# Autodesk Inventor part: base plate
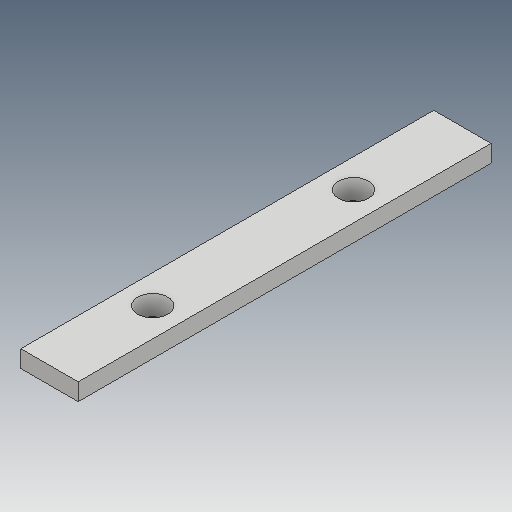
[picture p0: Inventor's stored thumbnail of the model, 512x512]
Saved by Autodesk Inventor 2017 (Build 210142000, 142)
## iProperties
Created: 2016-03
Part Number: base plate
Material: Generic
Document SubType Name: Modeling
Designer: Sandeep
Density: 1 g/cm^3
Appearance: Default
Author: Sandeep
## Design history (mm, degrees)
sketch "Sketch1"
  geometry: L1 (0, 0)-(144, 0); L2 (144, 0)-(144, 20); L3 (144, 20)-(0, 20); L4 (0, 20)-(0, 0)
  constraints: 8 end point, 2 parallel, 1 horizontal, 1 perpendicular
  dimensions: "d0" = 144 distance of L1.start L1.end; "d1" = 20 distance of L1.end L2.end
extrude "Extrusion1" new body sketch "Sketch1" distance "d2" = 6; taper "d3" = 0 deg
sketch "Sketch2"
  geometry: L1 (0, 20)-(0, 0) reference; L2 (0, 10)-(181.292, 10); 2 further points
  constraints: 2 end point, 2 point on line, 1 horizontal, 1 midpoint
  dimensions: "d4" = 70 distance of point (108, 10) point (38, 10); "d5" = 38 distance from line of L1 point (38, 10)
hole "Hole1" sketch "Sketch2" at (38, 10), (108, 10) diameter "d6" = 6; stored, may be unused: countersink angle "d10" = 45 deg, drill point angle "d12" = 118 deg; dims "d7" = 6, "d8" = 10.5, "d9" = 2, "d11" = 8
body "Solid1"
